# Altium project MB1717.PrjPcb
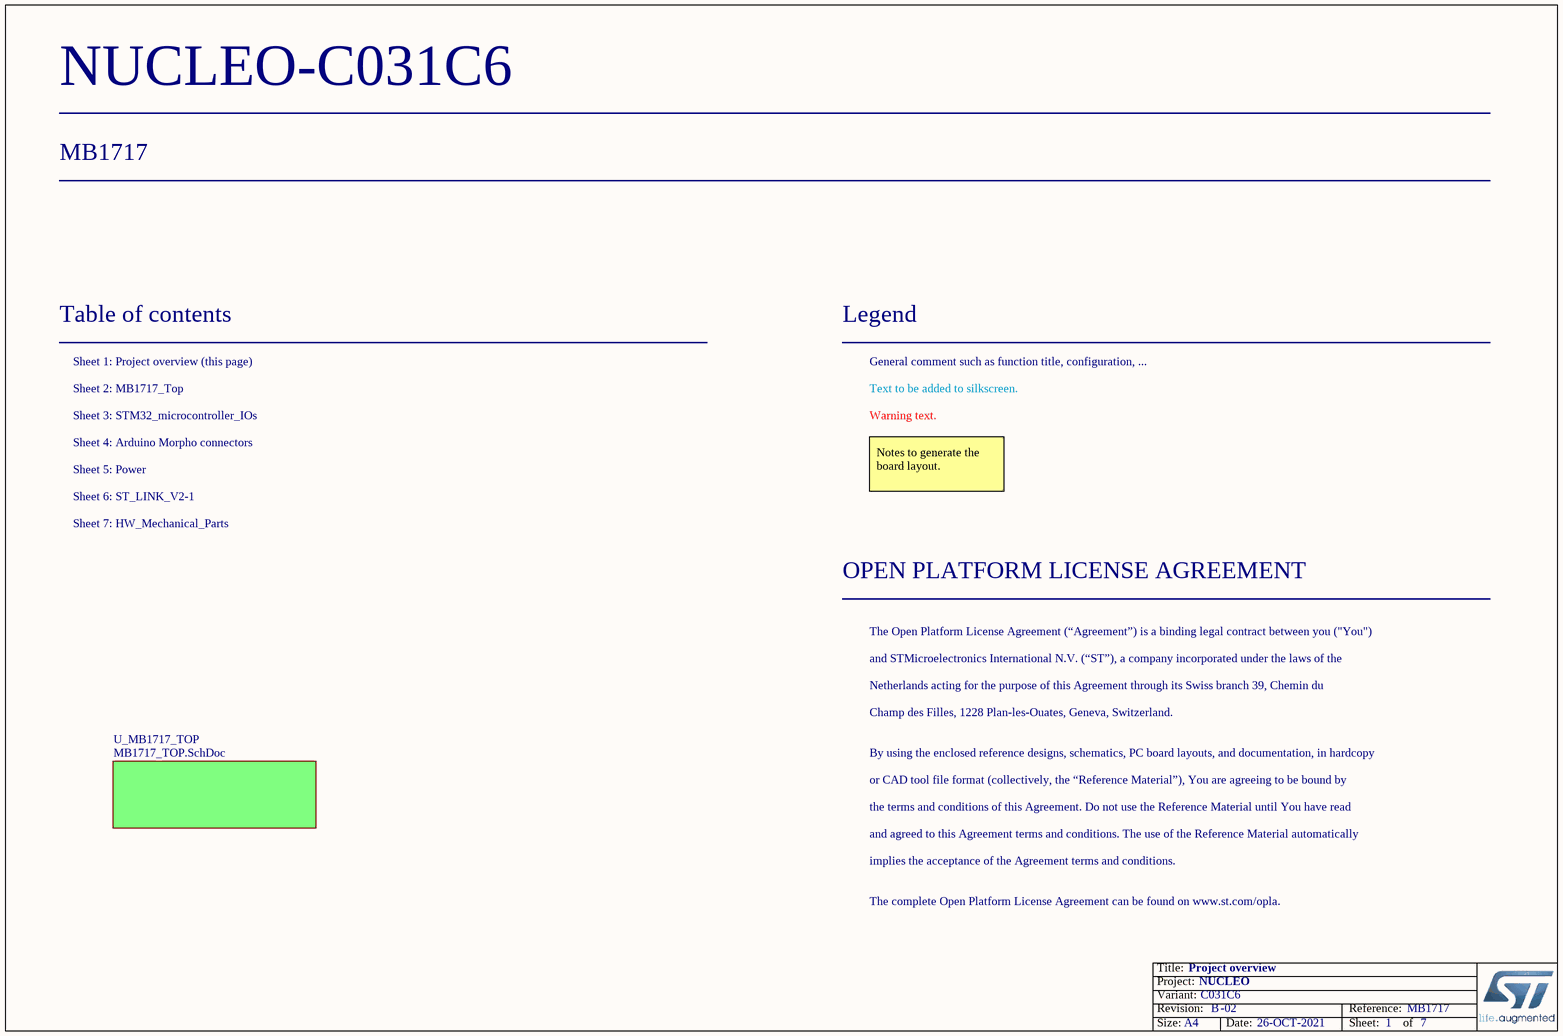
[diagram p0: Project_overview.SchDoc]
VariantName: C031C6; Board_Reference: MB1717; Board_PCB_Revision: B; Board_Name: NUCLEO; Board_Document_Date: 26-OCT-2021; Board_Assembly_Revision: 02
7 sheets, 150 parts. Net scope: flat (ports and power ports of the same name join across sheets).
Board file: MB1717.PcbDoc
Sheets:
  Project_overview.SchDoc
    U_MB1717_TOP = MB1717_TOP.SchDoc
      ST_LINK_V2-1 = ST_LINK_V2-1.SchDoc
      MCU = STM32_microcontroller_IOs.SchDoc
      Power = Power.SchDoc
      HW_Mechanical_Parts = HW_Mechanical_Parts.SchDoc
      U_Arduino_Morpho_connectors = Arduino_Morpho_connectors.SchDoc

## Sheet Project_overview.SchDoc: Project overview
size A4; Date: Not used; ApprovedBy: Not used; CheckedBy: Not used; Author: Not used; CompanyName: STMicroelectronics; DrawnBy: Not used; Engineer: Not used; Organization: Not used; Address1: Not used; Address2: Not used; Address3: Not used; Address4: Not used; DocumentNumber: 1; Revision: Not used; SheetNumber: 1; SheetTotal: 7

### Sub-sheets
U_MB1717_TOP = MB1717_TOP.SchDoc: no entries

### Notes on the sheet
- Table of contents
- Sheet 1: Project overview (this page)
- Legend
- General comment such as function title, configuration, ...
- Sheet 2: MB1717_Top
- Sheet 4: Arduino Morpho connectors
- Sheet 3: STM32_microcontroller_IOs
- Text to be added to silkscreen.
- Warning text.
- Sheet 5: Power
- Sheet 6: ST_LINK_V2-1
- Notes to generate the board layout.
- Sheet 7: HW_Mechanical_Parts
- OPEN PLATFORM LICENSE AGREEMENT
- The Open Platform License Agreement (“Agreement”) is a binding legal contract between you ("You")
- and STMicroelectronics International N.V. (“ST”), a company incorporated under the laws of the
- Netherlands acting for the purpose of this Agreement through its Swiss branch 39, Chemin du
- Champ des Filles, 1228 Plan-les-Ouates, Geneva, Switzerland.
- By using the enclosed reference designs, schematics, PC board layouts, and documentation, in hardcopy
- or CAD tool file format (collectively, the “Reference Material”), You are agreeing to be bound by
- the terms and conditions of this Agreement. Do not use the Reference Material until You have read
- and agreed to this Agreement terms and conditions. The use of the Reference Material automatically
- implies the acceptance of the Agreement terms and conditions.
- The complete Open Platform License Agreement can be found on www.st.com/opla.

## Sheet MB1717_TOP.SchDoc: TOP
size A4; CompanyName: STMicroelectronics; Organization: Microcontrollers Division; SheetNumber: 2; SheetTotal: 7
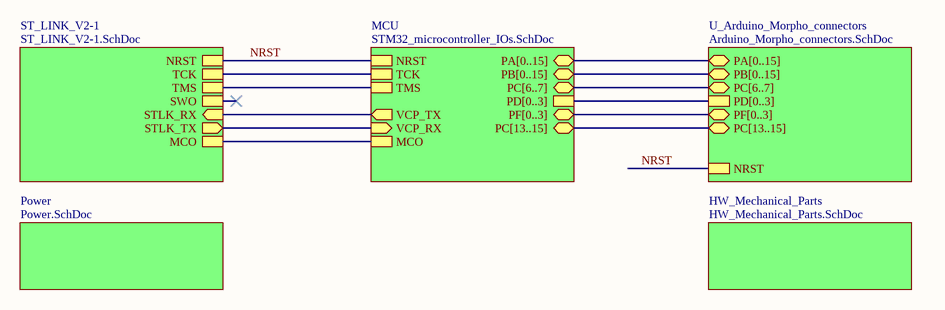
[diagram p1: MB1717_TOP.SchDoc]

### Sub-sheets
HW_Mechanical_Parts = HW_Mechanical_Parts.SchDoc: no entries
MCU = STM32_microcontroller_IOs.SchDoc: NRST, MCO, PA[0..15] (bidir), PB[0..15] (bidir), TCK, TMS, PD[0..3], PC[6..7] (bidir), PC[13..15] (bidir), VCP_RX (in), VCP_TX (out), PF[0..3] (bidir)
Power = Power.SchDoc: no entries
ST_LINK_V2-1 = ST_LINK_V2-1.SchDoc: TMS, TCK, MCO, NRST, STLK_RX (in), STLK_TX (out), SWO
U_Arduino_Morpho_connectors = Arduino_Morpho_connectors.SchDoc: PA[0..15] (bidir), PB[0..15] (bidir), NRST, PD[0..3], PC[6..7] (bidir), PC[13..15] (bidir), PF[0..3] (bidir)

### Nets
NRST: sheet ST_LINK_V2-1/NRST, sheet MCU/NRST, sheet U_Arduino_Morpho_connectors/NRST
(unnamed): sheet ST_LINK_V2-1/TMS, sheet MCU/TMS
(unnamed): sheet ST_LINK_V2-1/TCK, sheet MCU/TCK  [a separate net that carries the same name]
(unnamed): sheet ST_LINK_V2-1/MCO, sheet MCU/MCO  [a separate net that carries the same name]
(unnamed): sheet ST_LINK_V2-1/STLK_RX, sheet MCU/VCP_TX  [a separate net that carries the same name]
(unnamed): sheet ST_LINK_V2-1/STLK_TX, sheet MCU/VCP_RX  [a separate net that carries the same name]

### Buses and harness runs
bus sheet MCU/PA[0..15] = sheet U_Arduino_Morpho_connectors/PA[0..15]
bus sheet MCU/PB[0..15] = sheet U_Arduino_Morpho_connectors/PB[0..15]
bus sheet MCU/PC[6..7] = sheet U_Arduino_Morpho_connectors/PC[6..7]
bus sheet MCU/PC[13..15] = sheet U_Arduino_Morpho_connectors/PC[13..15]
bus sheet MCU/PD[0..3] = sheet U_Arduino_Morpho_connectors/PD[0..3]
bus sheet MCU/PF[0..3] = sheet U_Arduino_Morpho_connectors/PF[0..3]

## Sheet ST_LINK_V2-1.SchDoc: ST_LINK_V2-1
size A4; CompanyName: STMicroelectronics; Organization: Microcontrollers Division; SheetNumber: 6; SheetTotal: 7
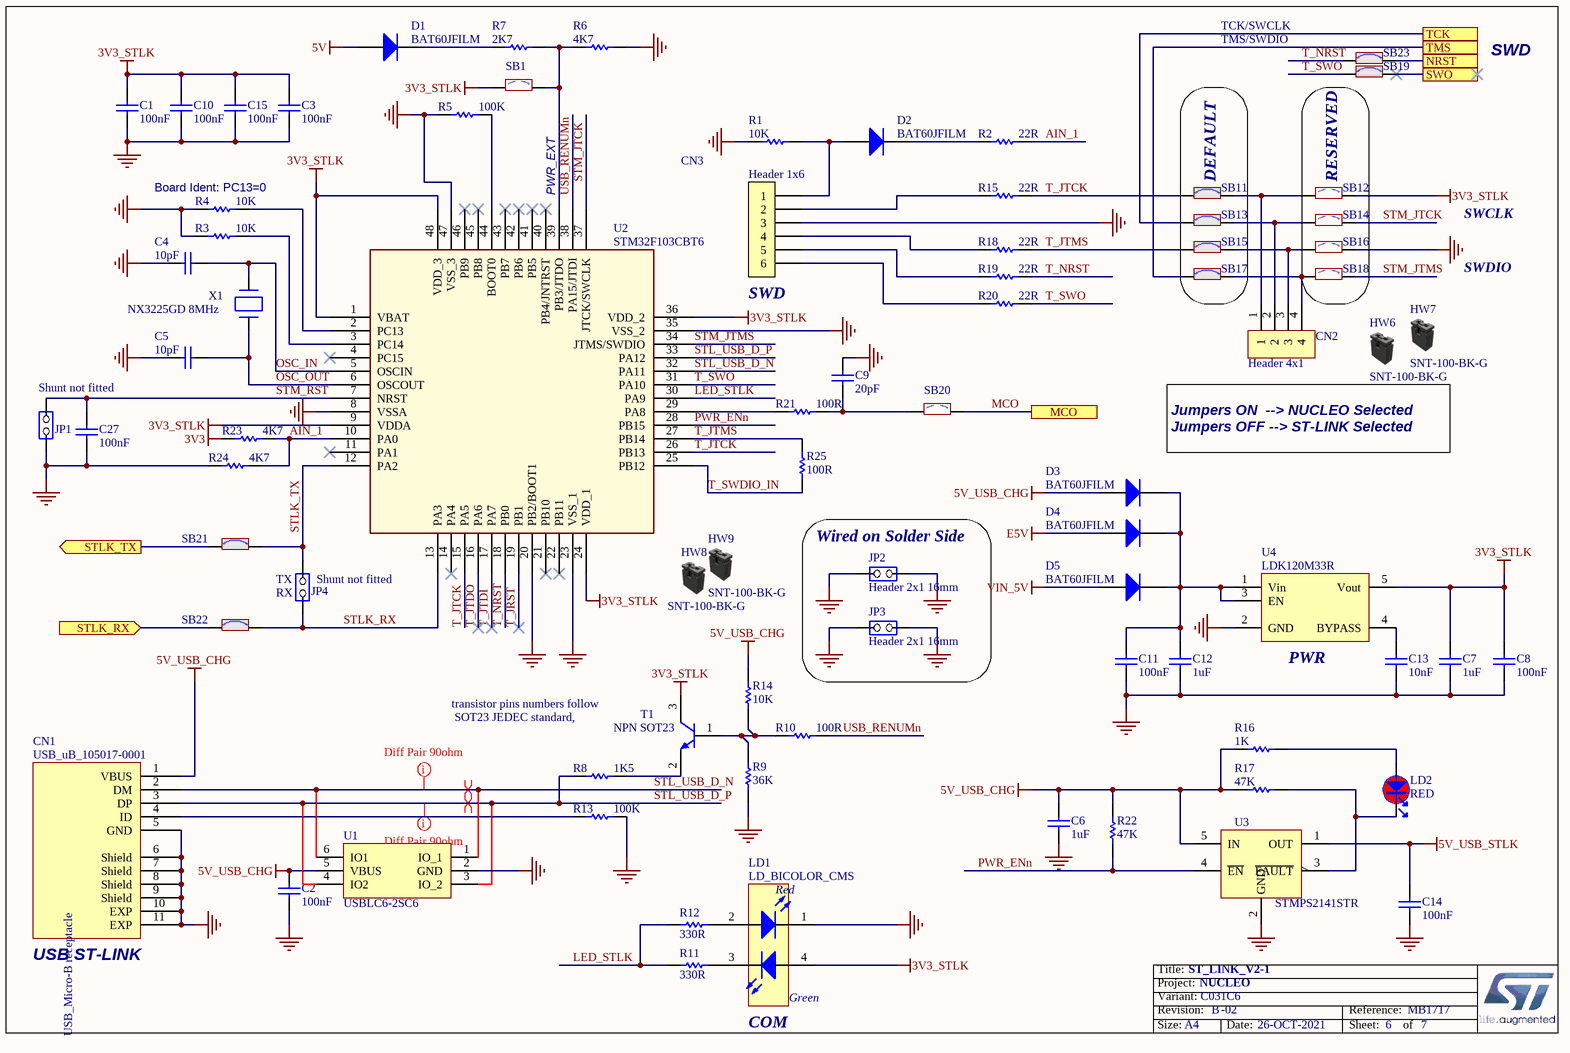
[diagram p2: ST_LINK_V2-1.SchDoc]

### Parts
C1  value 100nF  [C0603]  (hidden comment: Capacitor)
C2  value 100nF  [C0603]  (hidden comment: Capacitor)
C3  value 100nF  [C0603]  (hidden comment: Capacitor)
C4  value 10pF  [C0603]  (hidden comment: Capacitor)
C5  value 10pF  [C0603]  (hidden comment: Capacitor)
C6  value 1uF  [C0603]  (hidden comment: Capacitor)
C7  value 1uF  [C0603]  (hidden comment: Capacitor)
C8  value 100nF  [C0603]  (hidden comment: Capacitor)
C9  value 20pF  [C0603]  (hidden comment: Capacitor)
C10  value 100nF  [C0603]  (hidden comment: Capacitor)
C11  value 100nF  [C0603]  (hidden comment: Capacitor)
C12  value 1uF  [C0603]  (hidden comment: Capacitor)
C13  value 10nF  [C0603]  (hidden comment: Capacitor)
C14  value 100nF  [C0603]  (hidden comment: Capacitor)
C15  value 100nF  [C0603]  (hidden comment: Capacitor)
C27  value 100nF  [C0603]  (hidden comment: Capacitor)
CN1  value USB_uB_105017-0001  [CON_USBMICROB_MOLEX_105017-0001_H2P90]  (hidden comment: USB_uB_105017.0001)
CN2  Header 4x1  [CON_988-JIUBABA_PHFS25-11-04-G0B115-T-1]
CN3  value Header 1x6  [CON_988-JIUBABA_PHFS25-11-06-G0B115-T-1]  (hidden comment: Header 6x1)
D1  BAT60JFILM  [DIO_SOD323]
D2  BAT60JFILM  [DIO_SOD323]
D3  BAT60JFILM  [DIO_SOD323]
D4  BAT60JFILM  [DIO_SOD323]
D5  BAT60JFILM  [DIO_SOD323]
HW6  value SNT-100-BK-G  (hidden comment: Shunt Black 2.54mm)  (mechanical)
HW7  value SNT-100-BK-G  (hidden comment: Shunt Black 2.54mm)  (mechanical)
HW8  value SNT-100-BK-G  (hidden comment: Shunt Black 2.54mm)  (mechanical)
HW9  value SNT-100-BK-G  (hidden comment: Shunt Black 2.54mm)  (mechanical)
JP1  value Shunt not fitted  [CON_SAMTEC_TSW-102-07-G-S]  (hidden comment: Jumper_Header 2x1)
JP2  value Header 2x1 16mm  [CON_SAMTEC_TSW-102-09-X-S]  (hidden comment: Jumper_Header 2x1)
JP3  value Header 2x1 16mm  [CON_SAMTEC_TSW-102-09-X-S]  (hidden comment: Jumper_Header 2x1)
JP4  value Shunt not fitted  [CON_SAMTEC_TSW-102-07-G-S]  (hidden comment: Jumper_Header 2x1)
LD1  LD_BICOLOR_CMS  [LED_BI-GR_HSMF-A201-A00J1]
LD2  value RED  [LED_0603_RED]  (hidden comment: LED_red)
R1  value 10K  [R0603]  (hidden comment: Resistor)
R2  value 22R  [R0603]  (hidden comment: Resistor)
R3  value 10K  [R0603]  (hidden comment: Resistor)
R4  value 10K  [R0603]  (hidden comment: Resistor)
R5  value 100K  [R0603]  (hidden comment: Resistor)
R6  value 4K7  [R0603]  (hidden comment: Resistor)
R7  value 2K7  [R0603]  (hidden comment: Resistor)
R8  value 1K5  [R0603]  (hidden comment: Resistor)
R9  value 36K  [R0603]  (hidden comment: Resistor)
R10  value 100R  [R0603]  (hidden comment: Resistor)
R11  value 330R  [R0603]  (hidden comment: Resistor)
R12  value 330R  [R0603]  (hidden comment: Resistor)
R13  value 100K  [R0603]  (hidden comment: Resistor)
R14  value 10K  [R0603]  (hidden comment: Resistor)
R15  value 22R  [R0603]  (hidden comment: Resistor)
R16  value 1K  [R0603]  (hidden comment: Resistor)
R17  value 47K  [R0603]  (hidden comment: Resistor)
R18  value 22R  [R0603]  (hidden comment: Resistor)
R19  value 22R  [R0603]  (hidden comment: Resistor)
R20  value 22R  [R0603]  (hidden comment: Resistor)
R21  value 100R  [R0603]  (hidden comment: Resistor)
R22  value 47K  [R0603]  (hidden comment: Resistor)
R23  value 4K7  [R0603]  (hidden comment: Resistor)
R24  value 4K7  [R0603]  (hidden comment: Resistor)
R25  value 100R  [R0603]  (hidden comment: Resistor)
SB1  SB_OFF  [SOLDER-BRIDGE_R0603-0R]  (value not drawn)
SB11  SB_ON  [SOLDER-BRIDGE_R0603-0R]  (value not drawn)
SB12  SB_OFF  [SOLDER-BRIDGE_R0603-0R]  (value not drawn)
SB13  SB_ON  [SOLDER-BRIDGE_R0603-0R]  (value not drawn)
SB14  SB_OFF  [SOLDER-BRIDGE_R0603-0R]  (value not drawn)
SB15  SB_ON  [SOLDER-BRIDGE_R0603-0R]  (value not drawn)
SB16  SB_OFF  [SOLDER-BRIDGE_R0603-0R]  (value not drawn)
SB17  SB_ON  [SOLDER-BRIDGE_R0603-0R]  (value not drawn)
SB18  SB_OFF  [SOLDER-BRIDGE_R0603-0R]  (value not drawn)
SB19  SB_ON  [SOLDER-BRIDGE_R0603-0R]  (value not drawn)
SB20  SB_OFF  [SOLDER-BRIDGE_R0603-0R]  (value not drawn)
SB21  SB_ON  [SOLDER-BRIDGE_R0603-0R]  (value not drawn)
SB22  SB_ON  [SOLDER-BRIDGE_R0603-0R]  (value not drawn)
SB23  SB_ON  [SOLDER-BRIDGE_R0603-0R]  (value not drawn)
T1  value NPN SOT23  [NPN_SOT23]  (hidden comment: 9013-SOT23)
U1  USBLC6-2SC6  [ESD_SOT23-6L]
U2  STM32F103CBT6  [ICC_LQFP48_7X7_P050]
U3  STMPS2141STR  [MOS_SOT23-5L]
U4  LDK120M33R  [REG_SOT23-5L]
X1  value NX3225GD 8MHz  [CRY_NX3225GD_2P]  (hidden comment: XTAL_2_PINS)

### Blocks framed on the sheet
DEFAULT: SB11 SB13 SB15 SB17
RESERVED: SB12 SB14 SB16 SB18
Wired on Solder Side: JP2 JP3

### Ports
MCO, NRST, STLK_RX (in), STLK_TX (out), SWO, TCK, TMS

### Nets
3V3: R23.1
3V3_STLK: C1.2 C3.2 C7.2 C8.2 C10.2 C15.2 LD1.4(YellowGreen_anode) SB1.1 SB12.2 T1.3(C) U2.1(VBAT) U2.9(VDDA) U2.24(VDD_1) U2.36(VDD_2) U2.48(VDD_3) U4.5(Vout)
5V: D1.1(A)
5V_USB_CHG: C2.2 C6.2 CN1.1(VBUS) D3.1(A) R14.2 R16.2 R17.2 R22.2 U1.5(VBUS) U3.5(IN)
5V_USB_STLK: C14.2 U3.1(OUT)
E5V: D4.1(A)
GND: C1.1 C2.1 C3.1 C4.1 C5.1 C6.1 C7.1 C8.1 C9.2 C10.1 C11.1 C12.1 C13.1 C14.1 C15.1 C27.2 CN1.5(GND) CN1.6(Shield) CN1.7(Shield) CN1.8(Shield) CN1.9(Shield) CN1.10(EXP) CN1.11(EXP) CN3.3 JP1.2(NO) JP2.1(COMMON) JP2.2(NO) JP3.1(COMMON) JP3.2(NO) LD1.1(RED_cathode) R1.2 R3.1 R4.1 R5.1 R6.2 R9.1 R13.2 R24.1 SB16.2 U1.2(GND) U2.8(VSSA) U2.20(PB2/BOOT1) U2.23(VSS_1) U2.35(VSS_2) U2.47(VSS_3) U3.2(GND) U4.2(GND)
VIN_5V: D5.1(A)
AIN_1: R2.2 R23.2 R24.2 U2.10(PA0)
LED_STLK: R11.1 R12.1 U2.30(PA9)
MCO: SB20.2 ; port MCO
NRST: SB23.2 ; port NRST
OSC_IN: C4.2 U2.5(OSCIN) X1.2(X2)
OSC_OUT: C5.2 U2.6(OSCOUT) X1.1(X1)
PA13: SB17.1 ; port TMS
PA14: SB13.1 ; port TCK
PWR_ENn: R22.1 U2.28(PB15) U3.4(~{EN})
STL_USB_D_N: CN1.2(DM) U1.1(IO_1) U1.6(IO1) U2.32(PA11)
STL_USB_D_P: CN1.3(DP) R8.1 U1.3(IO_2) U1.4(IO2) U2.33(PA12)
STLK_RX: JP4.1(COMMON) SB22.2 U2.13(PA3)
STLK_TX: JP4.2(NO) SB21.2 U2.12(PA2)
STM_JTCK: SB14.2 U2.37(JTCK/SWCLK)
STM_JTMS: SB18.2 U2.34(JTMS/SWDIO)
STM_RST: C27.1 JP1.1(COMMON) U2.7(NRST)
T_JRST: U2.19(PB1)
T_JTCK: R15.2 SB11.1 U2.15(PA5) U2.26(PB13)
T_JTDI: U2.17(PA7)
T_JTDO: U2.16(PA6)
T_JTMS: R18.2 R25.2 SB15.1 U2.27(PB14)
T_NRST: R19.2 SB23.1 U2.18(PB0)
T_SWDIO_IN: R25.1 U2.25(PB12)
T_SWO: R20.2 SB19.1 U2.31(PA10)
USB_RENUMn: R10.2 U2.38(PA15/JTDI)
NetC9_1: C9.1 R21.2 SB20.1
NetC11_2: C11.2 C12.2 D3.2(K) D4.2(K) D5.2(K) U4.1(Vin) U4.3(EN)
NetC13_2: C13.2 U4.4(BYPASS)
NetCN1_4: CN1.4(ID) R13.1
NetCN2_1: CN2.1 SB11.2 SB12.1
NetCN2_2: CN2.2 SB13.2 SB14.1
NetCN2_3: CN2.3 SB15.2 SB16.1
NetCN2_4: CN2.4 SB17.2 SB18.1
NetCN3_1: CN3.1 D2.1(A) R1.1
NetCN3_2: CN3.2 R15.1
NetCN3_4: CN3.4 R18.1
NetCN3_5: CN3.5 R19.1
NetCN3_6: CN3.6 R20.1
NetD1_2: D1.2(K) R7.1
NetD2_2: D2.2(K) R2.1
NetLD1_2: LD1.2(Red_anode) R12.2
NetLD1_3: LD1.3(YellowGreen_cathode) R11.2
NetLD2_1: LD2.1 R16.1
NetLD2_2: LD2.2 R17.1 U3.3(~{FAULT})
NetR3_2: R3.2 U2.3(PC14)
NetR4_2: R4.2 U2.2(PC13)
NetR5_2: R5.2 U2.44(BOOT0)
NetR6_1: R6.1 R7.2 SB1.2 U2.39(PB3/JTDO)
NetR8_2: R8.2 T1.2(E)
NetR9_2: R9.2 R10.1 R14.1 T1.1(B)
NetR21_1: R21.1 U2.29(PA8)
NetSB19_2: SB19.2 ; port SWO
NetSB21_1: SB21.1 ; port STLK_TX
NetSB22_1: SB22.1 ; port STLK_RX

Not connected (* = marked no-connect by the designer): U2 4(PC15)* 11(PA1)* 14(PA4)* 21(PB10)* 22(PB11)* 40(PB4/JNTRST)* 41(PB5)* 42(PB6)* 43(PB7)* 45(PB8)* 46(PB9)*

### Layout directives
mark named Diff Pair 90ohm: STL_USB_D_N, STL_USB_D_P
differential pair: STL_USB_D_N, STL_USB_D_P

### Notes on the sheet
- TCK/SWCLK
- TMS/SWDIO
- SWD
- (near R4) Board Ident: PC13=0
- PWR_EXT
- SWCLK
- (near CN3) SWD
- SWDIO
- Jumpers ON  --> NUCLEO Selected
  Jumpers OFF --> ST-LINK Selected
- (near JP4) TX
- (near JP4) RX
- (near U4) PWR
- (near T1) transistor pins numbers follow
  SOT23 JEDEC standard,
- (near CN1) USB ST-LINK
- COM

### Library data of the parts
C1-C3 C8 C10 C11 C14 C15 C27 = MCD-00211: Capacitor, MLCC, 100nF, 16V, X7R, +/-10%, 0603, T=0,8mm; Manufacturer_Part_Number: CC0603KRX7R7BB104; Manufacturer: YAGEO; Alternate_Manufacturer_Part_Number: GCM155R71C104KA55D; Alternate_Manufacturer: MURATA; Part_Preference: Recommended; ECCN_US: EAR99; ECCN_EU: NEC; Provided_By: SUBCO; Order_Code_RS: 669-8763
C4 C5 = MCD-00637: Capacitor, MLCC, 10pF, 50V, NPO, +/-5%, 0603, T=0,8mm; Manufacturer_Part_Number: CC0603JRNPO9BN100; Manufacturer: YAGEO; Alternate_Manufacturer_Part_Number: GCM155R71C104KA55D; Alternate_Manufacturer: MURATA; Part_Preference: Recommended; ECCN_US: EAR99; ECCN_EU: NEC; Provided_By: SUBCO
C6 C7 C12 = MCD-00010: Capacitor, MLCC, 1uF, 16V, X5R, +/-10%, 0603, T=0,8mm; Manufacturer_Part_Number: CC0603KRX5R7BB105; Manufacturer: YAGEO; Alternate_Manufacturer_Part_Number: GCM155R71C104KA55D; Alternate_Manufacturer: MURATA; Part_Preference: Recommended; ECCN_US: EAR99; ECCN_EU: NEC; Provided_By: SUBCO
C9 = MCD-00638: Capacitor, MLCC, 20pF, 50V, NPO, +/-5%, 0603, T=0,8mm; Manufacturer_Part_Number: CC0603JRNPO9BN200; Manufacturer: YAGEO; Alternate_Manufacturer_Part_Number: GCM155R71C104KA55D; Alternate_Manufacturer: MURATA; Part_Preference: Recommended; ECCN_US: EAR99; ECCN_EU: NEC; Provided_By: SUBCO
C13 = MCD-00017: Capacitor, MLCC, 10nF, 50V, X7R, +/-10%, 0603, T=0.8mm; Manufacturer_Part_Number: CC0603KRX7R9BB103; Manufacturer: YAGEO; Alternate_Manufacturer_Part_Number: GCM155R71C104KA55D; Alternate_Manufacturer: MURATA; Part_Preference: Recommended; ECCN_US: EAR99; ECCN_EU: NEC; Provided_By: SUBCO; Order_Code_RS: 616-9537
CN1 = MCD-00028: USB-MICRO-B, 0.65mm, RA, SMT, Bottom Mount,; Part_Type: Connector; Manufacturer_Part_Number: 1050170001; Manufacturer: MOLEX; Part_Preference: Recommended; Provided_By: SUBCO
CN2 = MCD-00313: Header, 4x1, 2.54mm, VR, TH, Height 6mm/3mm; Part_Type: Connector; Manufacturer_Part_Number: PHFS25-11-04-G0B115-T-1; Manufacturer: JIUBABA; Alternate_Manufacturer_Part_Number: 313104S1411160; Alternate_Manufacturer: LIANYI; Part_Preference: Not recommended
CN3 = MCD-00316: Header, 6x1, 2.54mm, VR, TH, Height 6mm/3mm; Part_Type: Connector; Manufacturer_Part_Number: PHFS25-11-06-G0B115-T-1; Manufacturer: JIUBABA; Alternate_Manufacturer_Part_Number: 313106S1411160; Alternate_Manufacturer: LIANYI; Part_Preference: Not recommended; Provided_By: SUBCO
D1 = MCD-00034: Manufacturer: STMICROELECTRONICS; Part_Type: Diode; BMS_Part_Number: 9151097; Part_Preference: Recommended; Manufacturer_HQ_COO: EU; ECCN_US: EAR99; ECCN_EU: NEC; Provided_By: Subcon; Initial_Board_Reference: mb1274
D2-D5 = MCD-00034: Part_Type: Diode; Manufacturer: STMICROELECTRONICS; BMS_Part_Number: 9151097; Part_Preference: Recommended; Manufacturer_HQ_COO: EU; ECCN_US: EAR99; ECCN_EU: NEC; Provided_By: Subcon; Initial_Board_Reference: mb1274
HW6-HW9 = MCD-00043: SHUNT 2.54mm BLACK; Manufacturer: SAMTEC; Part_Type: Misc; Alternate_Manufacturer_Part_Number: 316102S111A; Alternate_Manufacturer: JIUBABA; Part_Preference: Recommended
JP1 JP4 = MCD-00045: Header, 2x1, 2,54mm, VR, TH, Height 5.84mm/2.54mm; Part_Type: Connector; Manufacturer_Part_Number: TSW-102-07-G-S; Manufacturer: SAMTEC; Alternate_Manufacturer_Part_Number: 313102S111116;313102S111116; Alternate_Manufacturer: JIUBABA; LIANYI; Part_Preference: Recommended
JP2 JP3 = MCD-00214: Header, 2x1, 2,54mm, VR, TH, Height 5.84mm/10.16mm; Part_Type: Connector; Manufacturer_Part_Number: TSW-102-09-G-S; Manufacturer: SAMTEC; Part_Preference: Recommended
LD1 = MCD-02402: LED Bicolor; Part_Type: Display; Manufacturer_Part_Number: 67-22sursygc-s530-a2-tr8; Manufacturer: EVERLIGHT; Alternate_Manufacturer_Part_Number: LE-RGW35280; Alternate_Manufacturer: EVERLUCK; Part_Preference: Alternate; Alternate_Internal_Part_Number: MCD-00051; ECCN_US: EAR99; ECCN_EU: NEC; Provided_By: SUBCO; Alternate_EMS: C
LD2 = MCD-00049: LED, Red, 0603; Manufacturer_Part_Number: 19-213-R6C-AP1Q2B/3T; Manufacturer: EVERLIGHT; Part_Type: Display; Alternate_Manufacturer_Part_Number: LS Q976-NR-1; Alternate_Manufacturer: OSRAM OPTO SEMICONDUCTORS; Part_Preference: Recommended; Provided_By: SUBCO
R1 R3 R4 R14 = MCD-00220: Resistor,10K,0603,1%,1/10W; Manufacturer_Part_Number: RC0603FR-0710KL; Manufacturer: YAGEO; Alternate_Manufacturer_Part_Number: RT0402FRE07100KL; Part_Preference: Recommended; ECCN_US: EAR99; ECCN_EU: NEC; Provided_By: SUBCO
R2 R15 R18-R20 = MCD-00066: Resistor,22R,0603,1%,1/10W; Manufacturer_Part_Number: RC0603FR-0722RL; Manufacturer: YAGEO; Alternate_Manufacturer_Part_Number: RT0402FRE07100KL; Part_Preference: Recommended; ECCN_US: EAR99; ECCN_EU: NEC; Provided_By: SUBCO
R5 R13 = MCD-00223: Resistor,100K,0603,1%,1/10W; Manufacturer_Part_Number: RC0603FR-07100KL; Manufacturer: YAGEO; Alternate_Manufacturer_Part_Number: RT0402FRE07100KL; Part_Preference: Recommended; ECCN_US: EAR99; ECCN_EU: NEC; Provided_By: SUBCO
R6 R23 R24 = MCD-00219: Resistor,4K7,0603,1%,1/10W; Manufacturer_Part_Number: RC0603FR-074K7L; Manufacturer: YAGEO; Alternate_Manufacturer_Part_Number: RT0402FRE07100KL; Part_Preference: Recommended; ECCN_US: EAR99; ECCN_EU: NEC; Provided_By: SUBCO
R7 = MCD-00218: Resistor,2K7,0603,1%,1/10W; Manufacturer_Part_Number: RC0603FR-072K7L; Manufacturer: YAGEO; BMS_Part_Number: 9129767; Alternate_Manufacturer_Part_Number: RT0402FRE07100KL; Part_Preference: Recommended; ECCN_US: EAR99; ECCN_EU: NEC; Provided_By: SUBCO
R8 = MCD-00217: Resistor,1K5,0603,1%,1/10W; Manufacturer_Part_Number: RC0603FR-071K5L; Manufacturer: YAGEO; BMS_Part_Number: 9129766; Alternate_Manufacturer_Part_Number: RT0402FRE07100KL; Part_Preference: Recommended; ECCN_US: EAR99; ECCN_EU: NEC; Provided_By: SUBCO
R9 = MCD-00221: Resistor,36K,0603,1%,1/10W; Manufacturer_Part_Number: RC0603FR-0736KL; Manufacturer: YAGEO; Alternate_Manufacturer_Part_Number: RT0402FRE07100KL; Part_Preference: Recommended; ECCN_US: EAR99; ECCN_EU: NEC; Provided_By: SUBCO
R10 R21 R25 = MCD-00224: Resistor,100R,0603,1%,1/10W; Manufacturer_Part_Number: RC0603FR-07100RL; Manufacturer: YAGEO; Alternate_Manufacturer_Part_Number: RT0402FRE07100KL; Part_Preference: Recommended; ECCN_US: EAR99; ECCN_EU: NEC; Provided_By: SUBCO
R11 R12 = MCD-00197: Resistor,330R,0603,1%,1/10W; Manufacturer_Part_Number: RC0603FR-07330RL; Manufacturer: YAGEO; BMS_Part_Number: 9129729; Alternate_Manufacturer_Part_Number: RT0402FRE07100KL; Part_Preference: Recommended; ECCN_US: EAR99; ECCN_EU: NEC; Provided_By: SUBCO
R16 = MCD-00070: Resistor,1K,0603,1%,1/10W; Manufacturer_Part_Number: RC0603FR-071KL; Manufacturer: YAGEO; Alternate_Manufacturer_Part_Number: RT0402FRE07100KL; Part_Preference: Recommended; ECCN_US: EAR99; ECCN_EU: NEC; Provided_By: SUBCO
R17 R22 = MCD-00222: Resistor,47K,0603,1%,1/10W; Manufacturer_Part_Number: RC0603FR-0747KL; Manufacturer: YAGEO; Alternate_Manufacturer_Part_Number: RT0402FRE07100KL; Part_Preference: Recommended; ECCN_US: EAR99; ECCN_EU: NEC; Provided_By: SUBCO
SB1 SB12 SB14 SB16 SB18 SB20 = MCD-00072: Solder Bridge OFF; Part_Type: Misc; Manufacturer_Part_Number: RC0603JR-070RL; Manufacturer: YAGEO; Part_Preference: Recommended
SB11 SB13 SB15 SB17 SB19 SB21-SB23 = MCD-00071: Solder Bridge ON; Part_Type: Misc; Manufacturer_Part_Number: RC0603JR-070RL; Manufacturer: YAGEO; Part_Preference: Recommended; Provided_By: SUBCO
T1 = MCD-00073: NPN Bipolar Transistor; Part_Type: IC; Manufacturer_Part_Number: BSR14; Manufacturer: ON SEMICONDUCTOR; Alternate_Manufacturer_Part_Number: MMBT2222LT1G / MMBT2222ALT1G / MMBT2222ALT3G; Part_Preference: Recommended; ECCN_US: EAR99; ECCN_EU: NEC; Provided_By: Subcon; Initial_Board_Reference: mb1274
U1 = MCD-00163: Very low capacitance ESD protection; Part_Type: IC; Manufacturer: STMICROELECTRONICS; BMS_Part_Number: 9151075; Part_Preference: Recommended; Manufacturer_HQ_COO: EU
U2 = MCD-00085: Medium-density performance line ARM-based 32-bit MCU with 128KB Flash; Manufacturer: STMICROELECTRONICS; Part_Type: IC; BMS_Part_Number: 9175111; Part_Preference: Recommended; Manufacturer_HQ_COO: EU; ECCN_US: 3A991A2; ECCN_EU: NEC; Provided_By: SUBCO with ST control
U3 = MCD-00083: Enhanced single channel power switches with active low enable pin; Part_Type: IC; Manufacturer: STMICROELECTRONICS; Alternate_Manufacturer_Part_Number: TPS2041C; Alternate_Manufacturer: TEXAS INSTRUMENTS; BMS_Part_Number: 9159003; Part_Preference: Recommended; Manufacturer_HQ_COO: EU
U4 = MCD-00663: 200 mA low quiescent current very low noise LDO; Part_Type: IC; Manufacturer: STMICROELECTRONICS; BMS_Part_Number: 9176330; Part_Preference: Recommended; Manufacturer_HQ_COO: EU
X1 = MCD-00092: Crystal 8MHz, 8pF, +-20ppm, 500ohms max,  SMD; Part_Type: Crystal oscillator; Manufacturer_Part_Number: NX3225GD 8MHz EXS00A-CG04874; Manufacturer: NDK; BMS_Part_Number: 9157029; Part_Preference: Recommended; ECCN_US: EAR99; ECCN_EU: NEC; Provided_By: SUBCO

## Sheet STM32_microcontroller_IOs.SchDoc: STM32_microcontroller_IOs
size A4; CompanyName: STMicroelectronics; Organization: Microcontrollers Division; SheetNumber: 3; SheetTotal: 7
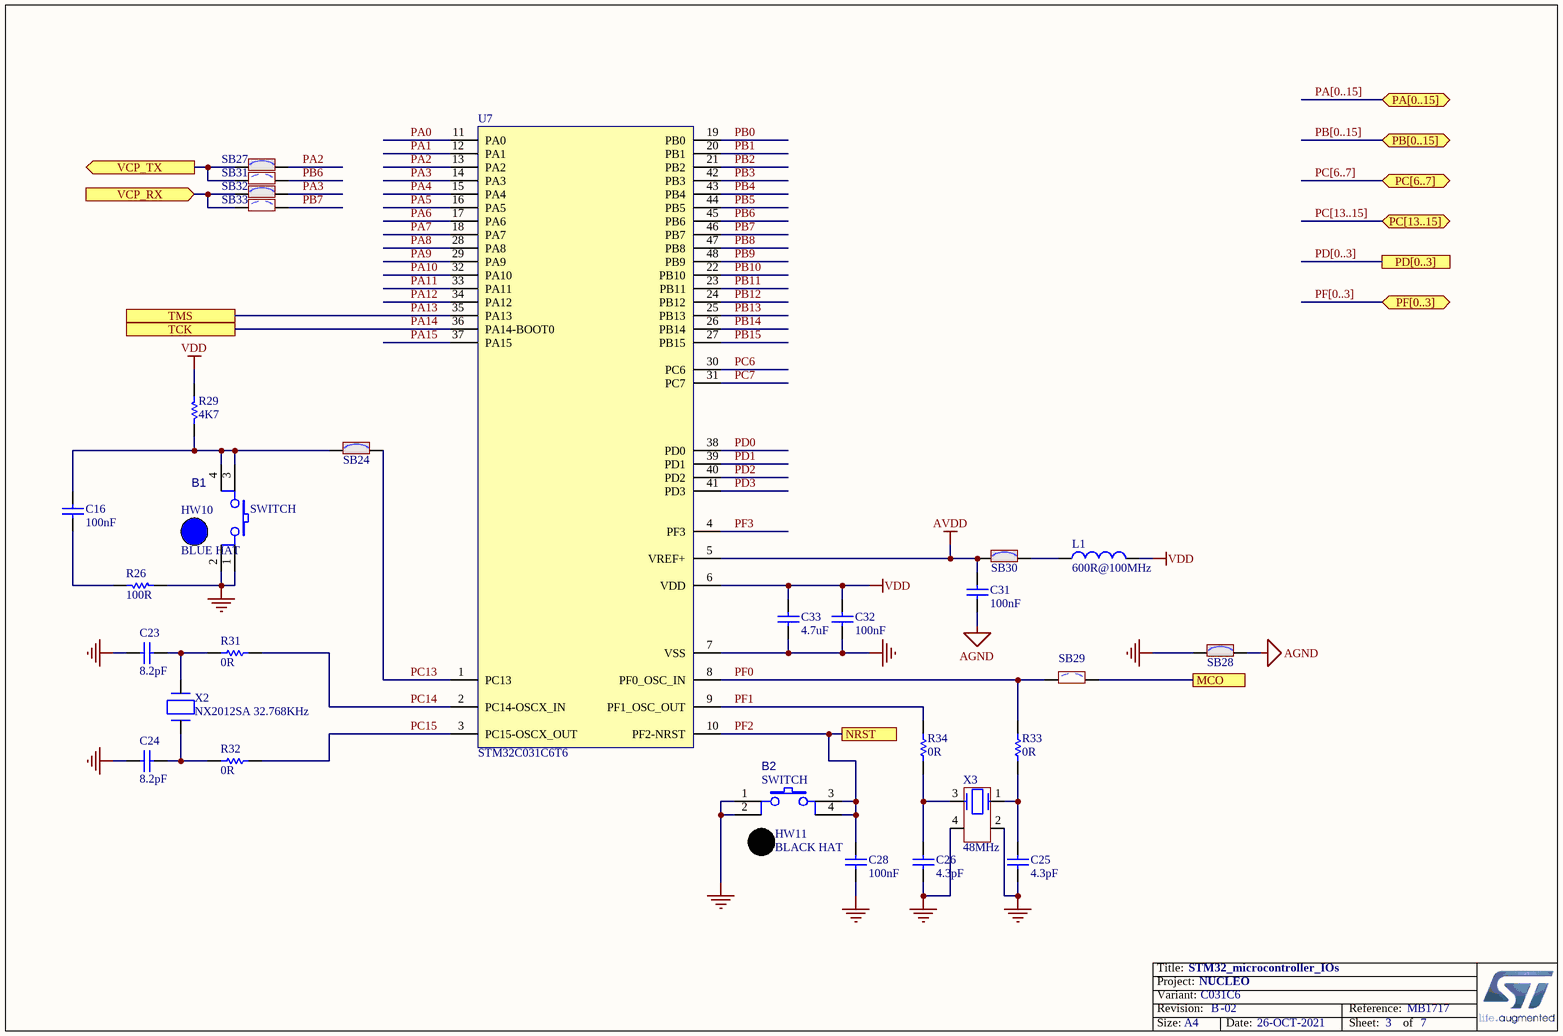
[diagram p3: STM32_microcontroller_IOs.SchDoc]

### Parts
B1  value SWITCH  [SWI_WEALTHMETAL_TD-0341_4P_BLUE]  (hidden comment: SW_PUSH_SMD)
B2  value SWITCH  [SWI_WEALTHMETAL_TD-0341_4P_BLACK]  (hidden comment: SW_PUSH_SMD)
C16  value 100nF  [C0603]  (hidden comment: Capacitor)
C23  value 8.2pF  [C0402]  (hidden comment: Capacitor)
C24  value 8.2pF  [C0402]  (hidden comment: Capacitor)
C25  value 4.3pF  [C0402]  (hidden comment: Capacitor)
C26  value 4.3pF  [C0402]  (hidden comment: Capacitor)
C28  value 100nF  [C0603]  (hidden comment: Capacitor)
C31  value 100nF  [C0603]  (hidden comment: Capacitor)
C32  value 100nF  [C0603]  (hidden comment: Capacitor)
C33  value 4.7uF  [C0603]  (hidden comment: Capacitor)
HW10  value BLUE HAT  (hidden comment: BUTTON_HAT_BLUE)  (mechanical)
HW11  value BLACK HAT  (hidden comment: BUTTON_HAT_BLACK)  (mechanical)
L1  value 600R@100MHz  [L0603]  (hidden comment: BEAD)
R26  value 100R  [R0603]  (hidden comment: Resistor)
R29  value 4K7  [R0603]  (hidden comment: Resistor)
R31  value 0R  [R0402]  (hidden comment: Resistor)
R32  value 0R  [R0402]  (hidden comment: Resistor)
R33  value 0R  [R0402]  (hidden comment: Resistor)
R34  value 0R  [R0402]  (hidden comment: Resistor)
SB24  SB_ON  [SOLDER-BRIDGE_R0603-0R]  (value not drawn)
SB27  SB_ON  [SOLDER-BRIDGE_R0603-0R]  (value not drawn)
SB28  SB_ON  [SOLDER-BRIDGE_R0603-0R]  (value not drawn)
SB29  SB_OFF  [SOLDER-BRIDGE_R0603-0R]  (value not drawn)
SB30  SB_ON  [SOLDER-BRIDGE_R0603-0R]  (value not drawn)
SB31  SB_OFF  [SOLDER-BRIDGE_R0603-0R]  (value not drawn)
SB32  SB_ON  [SOLDER-BRIDGE_R0603-0R]  (value not drawn)
SB33  SB_OFF  [SOLDER-BRIDGE_R0603-0R]  (value not drawn)
U7  STM32C031C6T6  [ICC_LQFP48_7X7_P050]
X2  value NX2012SA 32.768KHz  [CRY_NX2012SA_2P]  (hidden comment: XTAL_2_PINS)
X3  value 48MHz  [CRY_NX1612SA_4P]  (hidden comment: XTAL_4_PINS)

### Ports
MCO, NRST, PA[0..15] (bidir), PB[0..15] (bidir), PC[6..7] (bidir), PC[13..15] (bidir), PD[0..3], PF[0..3] (bidir), TCK, TMS, VCP_RX (in), VCP_TX (out)

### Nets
AGND: C31.1 SB28.2
AVDD: C31.2 SB30.1 U7.5(VREF+)
GND: B1.1 B1.2 B2.1 B2.2 C23.1 C24.1 C25.1 C26.1 C28.1 C32.1 C33.1 R26.1 SB28.1 U7.7(VSS) X3.2 X3.4
VDD: C32.2 C33.2 L1.2 R29.2 U7.6(VDD)
MCO: SB29.2 ; port MCO
PA0: U7.11(PA0)
PA1: U7.12(PA1)
PA2: SB27.2 U7.13(PA2)
PA3: SB32.2 U7.14(PA3)
PA4: U7.15(PA4)
PA5: U7.16(PA5)
PA6: U7.17(PA6)
PA7: U7.18(PA7)
PA8: U7.28(PA8)
PA9: U7.29(PA9)
PA10: U7.32(PA10)
PA11: U7.33(PA11)
PA12: U7.34(PA12)
PA13: U7.35(PA13) ; port TMS
PA14: U7.36(PA14-BOOT0) ; port TCK
PA15: U7.37(PA15)
PB0: U7.19(PB0)
PB1: U7.20(PB1)
PB2: U7.21(PB2)
PB3: U7.42(PB3)
PB4: U7.43(PB4)
PB5: U7.44(PB5)
PB6: SB31.2 U7.45(PB6)
PB7: SB33.2 U7.46(PB7)
PB8: U7.47(PB8)
PB9: U7.48(PB9)
PB10: U7.22(PB10)
PB11: U7.23(PB11)
PB12: U7.24(PB12)
PB13: U7.25(PB13)
PB14: U7.26(PB14)
PB15: U7.27(PB15)
PC6: U7.30(PC6)
PC7: U7.31(PC7)
PC13: SB24.1 U7.1(PC13)
PC14: R31.2 U7.2(PC14-OSCX_IN)
PC15: R32.2 U7.3(PC15-OSCX_OUT)
PD0: U7.38(PD0)
PD1: U7.39(PD1)
PD2: U7.40(PD2)
PD3: U7.41(PD3)
PF0: R33.2 SB29.1 U7.8(PF0_OSC_IN)
PF1: R34.2 U7.9(PF1_OSC_OUT)
PF2: B2.3 B2.4 C28.2 U7.10(PF2-NRST) ; port NRST  [project net NRST]
PF3: U7.4(PF3)
NetB1_3: B1.3 B1.4 C16.2 R29.1 SB24.2
NetC16_1: C16.1 R26.2
NetC23_2: C23.2 R31.1 X2.2(X2)
NetC24_2: C24.2 R32.1 X2.1(X1)
NetC25_2: C25.2 R33.1 X3.1
NetC26_2: C26.2 R34.1 X3.3
NetL1_1: L1.1 SB30.2
NetSB27_1: SB27.1 SB31.1 ; port VCP_TX
NetSB32_1: SB32.1 SB33.1 ; port VCP_RX

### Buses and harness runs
bus PA[0..15] = port PA[0..15]
bus PB[0..15] = port PB[0..15]
bus PC[6..7] = port PC[6..7]
bus PC[13..15] = port PC[13..15]
bus PD[0..3] = port PD[0..3]
bus PF[0..3] = port PF[0..3]

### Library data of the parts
B1 = MCD-00002: Push Button, NC, 0.1A, 24V, Blue; Part_Type: Misc; Manufacturer_Part_Number: TD-0341X-GO0; Manufacturer: WEALTHMETAL; Part_Preference: Not recommended
B2 = MCD-00001: Push Button, NC, 0.1A, 24V, Black; Part_Type: Misc; Manufacturer_Part_Number: TD-0341X-A00; Manufacturer: WEALTHMETAL; Part_Preference: Not recommended
C16 C28 C31 C32 = MCD-00211: as C1 on sheet ST_LINK_V2-1
C23 C24 = MCD-01932: Capacitor, MLCC, 8.2pF, 50V, NPO, +/- 0.25pF, 0402, T=0,5mm; Manufacturer_Part_Number: CC0402CRNPO9BN8R2; Manufacturer: YAGEO; Part_Preference: Recommended; ECCN_US: EAR99; ECCN_EU: NEC; Provided_By: SUBCO
C25 C26 = MCD-01706: Capacitor, MLCC, 4.3pF, 50V, NPO, +/-0.25pF, 0402, T=0,5mm; Manufacturer_Part_Number: CC0402CRNPO9BN4R3; Manufacturer: YAGEO; Alternate_Manufacturer_Part_Number: GCM155R71C104KA55D; Alternate_Manufacturer: MURATA; Part_Preference: Recommended; ECCN_US: EAR99; ECCN_EU: NEC; Provided_By: SUBCO
C33 = MCD-00009: Capacitor, MLCC, 4.7uF, 16V, X5R, +/-10%, 0603, T=0.8mm; Manufacturer_Part_Number: CC0603KRX5R7BB475; Manufacturer: YAGEO; Alternate_Manufacturer_Part_Number: GCM155R71C104KA55D; Alternate_Manufacturer: MURATA; Part_Preference: Recommended; ECCN_US: EAR99; ECCN_EU: NEC; Provided_By: SUBCO
HW10 = MCD-00634: Blue Hat for switch TD0341X-G01-BLU; Part_Type: Misc; Manufacturer_Part_Number: 988.16.09.3.00002_SH-517; Manufacturer: JIUBABA; Part_Preference: Not recommended
HW11 = MCD-00635: Black Hat for switch TD0341X-G01-BLA; Part_Type: Misc; Manufacturer_Part_Number: 988.16.09.3.00003_SH-517; Manufacturer: JIUBABA; Part_Preference: Not recommended
L1 = MCD-00047: SMD Chip ferrite bead, 600R@100MHz +/-25%, 350mA, 500mohm DC, 0603, T=0.8mm; Manufacturer_Part_Number: FCM1608KF-601T03; Manufacturer: TAI-TECH; Part_Type: Inductor; Part_Preference: Recommended; Provided_By: SUBCO
R26 = MCD-00224: as R10 on sheet ST_LINK_V2-1
R29 = MCD-00219: as R6 on sheet ST_LINK_V2-1
R31-R34 = MCD-00052: Resistor,0R,0402,5%,1/16W; Manufacturer_Part_Number: RC0402JR-070RL; Manufacturer: YAGEO; Alternate_Manufacturer_Part_Number: RT0402FRE07100KL; Part_Preference: Recommended; ECCN_US: EAR99; ECCN_EU: NEC; Provided_By: SUBCO; Order_Code_RS: 618-5804
SB24 SB27 SB28 SB30 SB32 = MCD-00071: as SB11 on sheet ST_LINK_V2-1
SB29 SB31 SB33 = MCD-00072: as SB1 on sheet ST_LINK_V2-1
U7 = MCD-02301: MCU, ARM™-based 32-bit MCU Cortex-M0+, 32KB Flash, 6KB SRAM; Part_Type: IC; Part_Preference: Recommended; Manufacturer: STMICROELECTRONICS
X2 = MCD-01479: Crystal 32.768kHz, 6pF, -+20ppm, 80Kohm max, SMD; Part_Type: Crystal oscillator; Manufacturer_Part_Number: NX2012SA 32.768KHz EXS00A-MU00527; Manufacturer: NDK; BMS_Part_Number: 9157049; Part_Preference: Recommended; ECCN_US: EAR99; ECCN_EU: NEC; Provided_By: SUBCO
X3 = MCD-02262: Crystal, 48MHz, 7pF, +/-20 ppm, 80R, 1.6x1.2mm; Part_Type: Crystal oscillator; Manufacturer_Part_Number: NX1612SA-48MHZ-EXS00A-CS13734; Manufacturer: NDK; BMS_Part_Number: 9157042; Part_Preference: Recommended; ECCN_US: EAR99; ECCN_EU: NEC; Provided_By: SUBCO

## Sheet Power.SchDoc: Power
size A4; CompanyName: STMicroelectronics; Organization: Microcontrollers Division; SheetNumber: 5; SheetTotal: 7
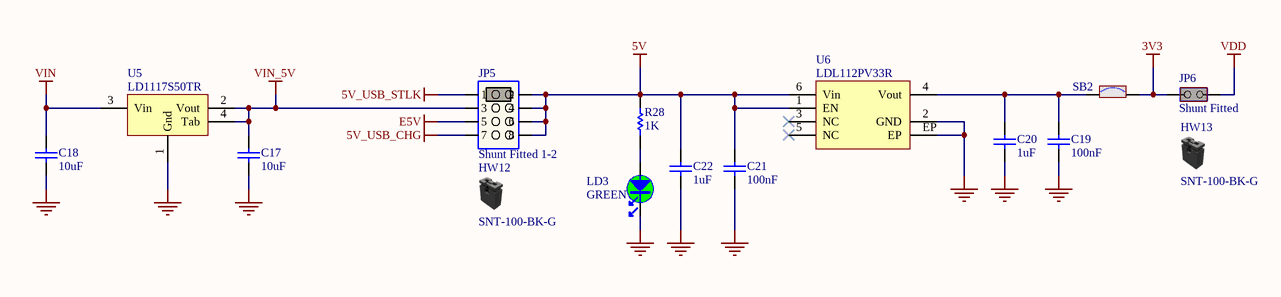
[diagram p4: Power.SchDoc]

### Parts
C17  value 10uF  [C0805]  (hidden comment: Capacitor)
C18  value 10uF  [C0805]  (hidden comment: Capacitor)
C19  value 100nF  [C0603]  (hidden comment: Capacitor)
C20  value 1uF  [C0603]  (hidden comment: Capacitor)
C21  value 100nF  [C0603]  (hidden comment: Capacitor)
C22  value 1uF  [C0603]  (hidden comment: Capacitor)
HW12  value SNT-100-BK-G  (hidden comment: Shunt Black 2.54mm)  (mechanical)
HW13  value SNT-100-BK-G  (hidden comment: Shunt Black 2.54mm)  (mechanical)
JP5  value Shunt Fitted 1-2  [CON_SAMTEC_TSW-104-07-X-D]  (hidden comment: Jumper_Header 4x2 Fitted 1-2)
JP6  value Shunt Fitted  [CON_SAMTEC_TSW-102-07-G-S]  (hidden comment: Jumper_Header 2x1 Fitted)
LD3  value GREEN  [LED_0603_GREEN]  (hidden comment: LED_green)
R28  value 1K  [R0603]  (hidden comment: Resistor)
SB2  SB_ON  [SOLDER-BRIDGE_R0603-0R]  (value not drawn)
U5  LD1117S50TR  [REG_SOT223-TAB]
U6  LDL112PV33R  [ICC_DFN6-EPAD_3X3_P095]

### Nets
3V3: JP6.2(NO) SB2.2
5V: C21.2 C22.2 JP5.2 JP5.4 JP5.6 JP5.8 R28.1 U6.1(EN) U6.6(Vin)
5V_USB_CHG: JP5.7
5V_USB_STLK: JP5.1
E5V: JP5.5
GND: C17.1 C18.1 C19.1 C20.1 C21.1 C22.1 LD3.2 U5.1(Gnd) U6.2(GND) U6.EP
VDD: JP6.1(COMMON)
VIN: C18.2 U5.3(Vin)
VIN_5V: C17.2 JP5.3 U5.2(Vout) U5.4(Tab)
NetC19_2: C19.2 C20.2 SB2.1 U6.4(Vout)
NetLD3_1: LD3.1 R28.2

Not connected (* = marked no-connect by the designer): U6 3(NC)* 5(NC)*

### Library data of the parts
C17 C18 = MCD-00014: Capacitor, MLCC, 10uF, 25V, X5R, +/-10%, 0805, T=0,85mm; Manufacturer_Part_Number: CC0805KRX5R8BB106; Manufacturer: YAGEO; Alternate_Manufacturer_Part_Number: GCM155R71C104KA55D; Alternate_Manufacturer: MURATA; Part_Preference: Recommended; ECCN_US: EAR99; ECCN_EU: NEC; Provided_By: SUBCO
C19 C21 = MCD-00211: as C1 on sheet ST_LINK_V2-1
C20 C22 = MCD-00010: as C6 on sheet ST_LINK_V2-1
HW12 HW13 = MCD-00043: as HW6 on sheet ST_LINK_V2-1
JP5 = MCD-00686: Header, 4x2, 2,54mm, VR, TH, Height 5.84mm/2.54mm - Shunt Fitted 1-2; Part_Type: Connector; Manufacturer_Part_Number: TSW-104-07-G-D; Manufacturer: SAMTEC; Part_Preference: Recommended
JP6 = MCD-00683: Header, 2x1, 2,54mm, VR, TH, Height 5.84mm/2.54mm - Shunt Fitted by default; Part_Type: Connector; Manufacturer_Part_Number: TSW-102-07-G-S; Manufacturer: SAMTEC; Alternate_Manufacturer_Part_Number: 313102S111116; Alternate_Manufacturer: LIANYI; Part_Preference: Recommended; Provided_By: SUBCO
LD3 = MCD-00050: LED, Green, 0603; Part_Type: Display; Manufacturer_Part_Number: 19-213SYGC/S530-E2/TR8; Manufacturer: EVERLIGHT; Alternate_Manufacturer_Part_Number: LG Q396-PS-35; Alternate_Manufacturer: OSRAM OPTO SEMICONDUCTORS; Part_Preference: Recommended; Provided_By: SUBCO; Order_Code_RS: 7730452
R28 = MCD-00070: as R16 on sheet ST_LINK_V2-1
SB2 = MCD-00071: as SB11 on sheet ST_LINK_V2-1
U5 = MCD-00088: IC REG LDO 5V 0.8A SOT223; Manufacturer: STMICROELECTRONICS; BMS_Part_Number: 9176133; Part_Preference: Recommended; Manufacturer_HQ_COO: EU; ECCN_US: EAR99; ECCN_EU: NEC; Provided_By: SUBCO with ST control
U6 = MCD-00664: 1.2 A low quiescent current LDO with reverse current protection; Part_Type: IC; Manufacturer: STMICROELECTRONICS; BMS_Part_Number: 9176253; Part_Preference: Recommended; Manufacturer_HQ_COO: EU

## Sheet HW_Mechanical_Parts.SchDoc: HW Mechanical parts
size A4; SheetNumber: 7; SheetTotal: 7
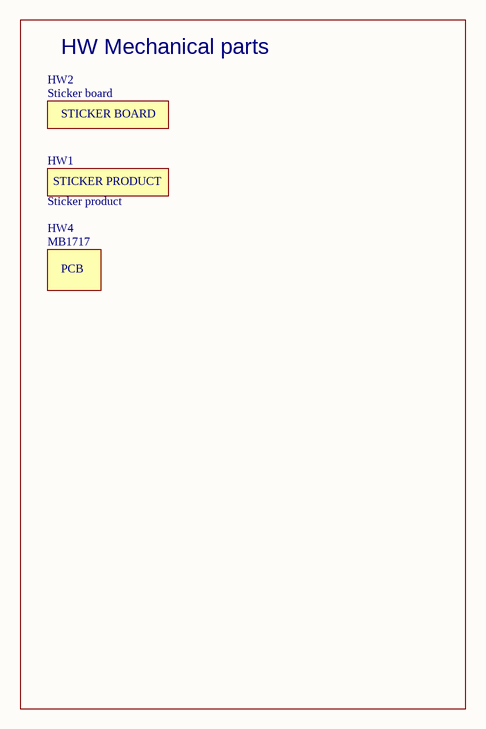
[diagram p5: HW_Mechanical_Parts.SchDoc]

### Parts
HW1  value Sticker product  [STICKER_PRODUCT_25X9]  (hidden comment: STICKER_PRODUCT)  (no BOM)
HW2  value Sticker board  [STICKER_BOARD_25X9]  (hidden comment: STICKER_BOARD)  (no BOM)
HW4  value MB1717  (hidden comment: PCB)  (mechanical)

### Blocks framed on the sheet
HW Mechanical parts: HW1 HW2 HW4

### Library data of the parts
HW1 = MCD-00547: Sticker product 25x9 mm; Part_Type: Misc; Part_Preference: Recommended
HW2 = MCD-00235: Sticker Board 25x9 mm; Part_Type: Misc; Part_Preference: Recommended
HW4 = MCD-02488: MB1717 PCB; Part_Preference: Recommended; Provided_By: SUBCO

## Sheet Arduino_Morpho_connectors.SchDoc: Connectors
size A4; CompanyName: STMicroelectronics; Organization: Microcontrollers Division; SheetNumber: 4; SheetTotal: 7
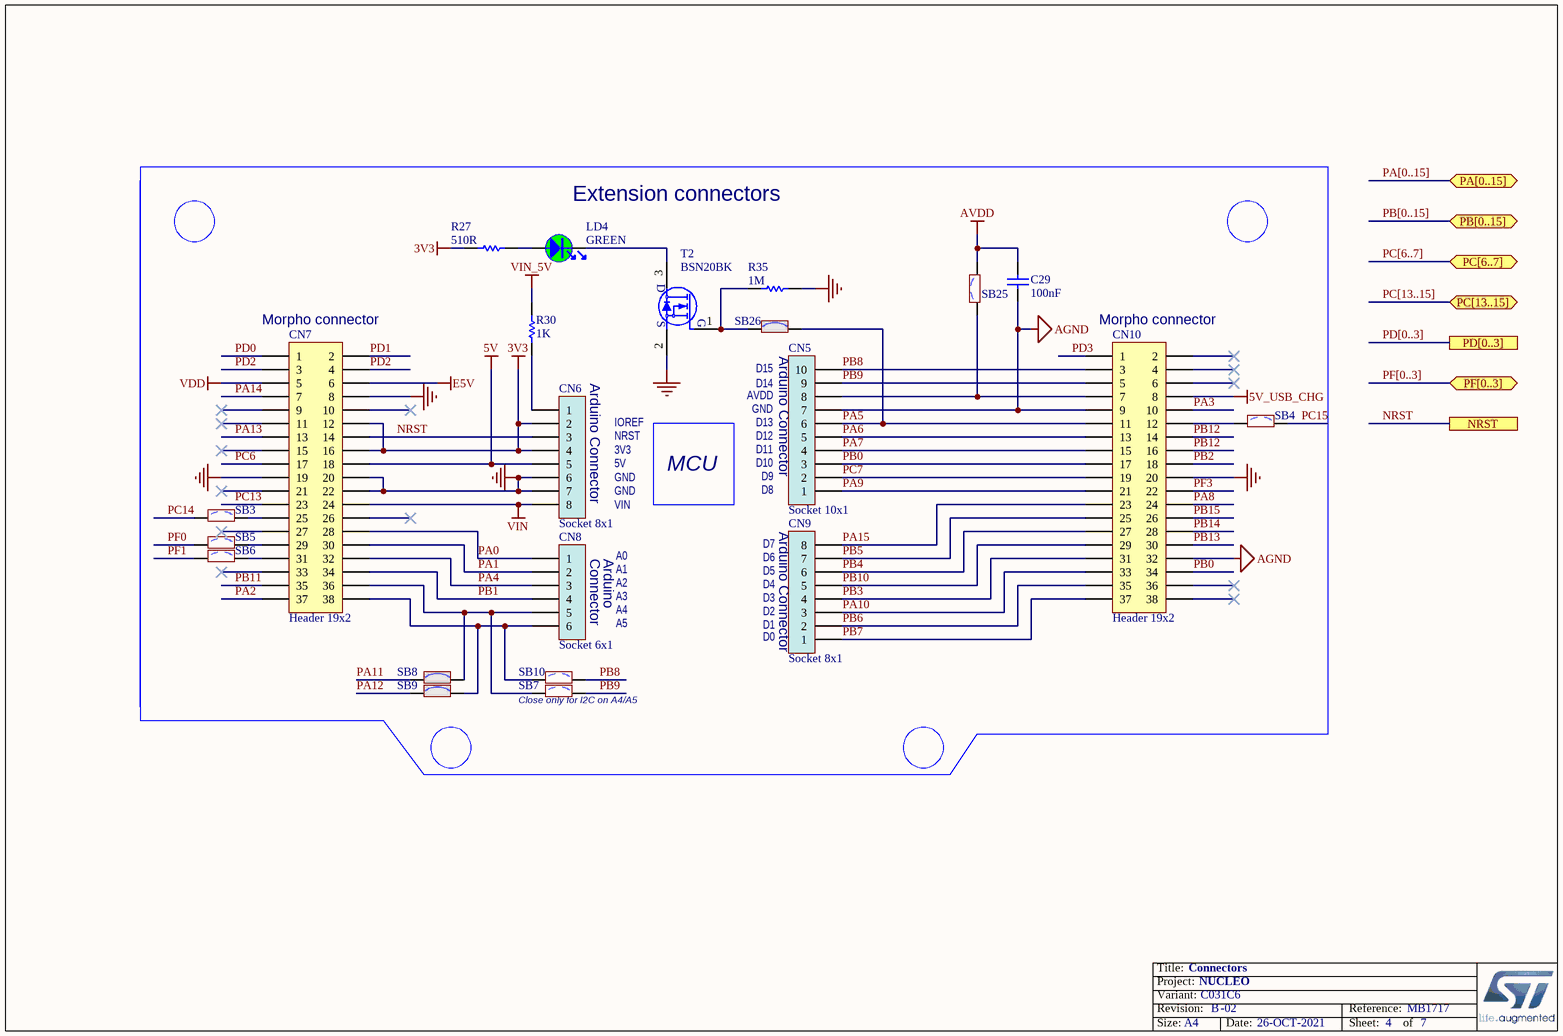
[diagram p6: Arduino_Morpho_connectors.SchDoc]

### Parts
C29  value 100nF  [C0603]  (hidden comment: Capacitor)
CN5  Socket 10x1  [CON_SAMTEC_SSW-110-03-X-S]
CN6  Socket 8x1  [CON_SAMTEC_SSW-108-03-X-S]
CN7  Header 19x2  [CON_SAMTEC_TSW-119-09-X-D]
CN8  Socket 6x1  [CON_SAMTEC_SSW-106-03-X-S]
CN9  Socket 8x1  [CON_SAMTEC_SSW-108-03-X-S]
CN10  Header 19x2  [CON_SAMTEC_TSW-119-09-X-D]
LD4  value GREEN  [LED_0603_GREEN]  (hidden comment: LED_green)
R27  value 510R  [R0603]  (hidden comment: Resistor)
R30  value 1K  [R0603]  (hidden comment: Resistor)
R35  value 1M  [R0603]  (hidden comment: Resistor)
SB3  SB_OFF  [SOLDER-BRIDGE_R0603-0R]  (value not drawn)
SB4  SB_OFF  [SOLDER-BRIDGE_R0603-0R]  (value not drawn)
SB5  SB_OFF  [SOLDER-BRIDGE_R0603-0R]  (value not drawn)
SB6  SB_OFF  [SOLDER-BRIDGE_R0603-0R]  (value not drawn)
SB7  SB_OFF  [SOLDER-BRIDGE_R0603-0R]  (value not drawn)
SB8  SB_ON  [SOLDER-BRIDGE_R0603-0R]  (value not drawn)
SB9  SB_ON  [SOLDER-BRIDGE_R0603-0R]  (value not drawn)
SB10  SB_OFF  [SOLDER-BRIDGE_R0603-0R]  (value not drawn)
SB25  SB_OFF  [SOLDER-BRIDGE_R0603-0R]  (value not drawn)
SB26  SB_ON  [SOLDER-BRIDGE_R0603-0R]  (value not drawn)
T2  value BSN20BK  [MOS_SOT23]  (hidden comment: BSN20)

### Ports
NRST, PA[0..15] (bidir), PB[0..15] (bidir), PC[6..7] (bidir), PC[13..15] (bidir), PD[0..3], PF[0..3] (bidir)

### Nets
3V3: CN6.2 CN6.4 CN7.12 CN7.16 R27.2
5V: CN6.5 CN7.18
5V_USB_CHG: CN10.8
AGND: C29.1 CN5.7 CN10.9 CN10.32
AVDD: C29.2 SB25.2
E5V: CN7.6
GND: CN6.6 CN6.7 CN7.8 CN7.19 CN7.20 CN7.22 CN10.20 R35.2 T2.2(S)
VDD: CN7.5
VIN: CN6.8 CN7.24
VIN_5V: R30.1
NRST: CN6.3 CN7.14 ; port NRST
PA0: CN7.28 CN8.1
PA1: CN7.30 CN8.2
PA2: CN7.37
PA3: CN10.10
PA4: CN7.32 CN8.3
PA5: CN5.6 CN10.11 SB26.2
PA6: CN5.5 CN10.13
PA7: CN5.4 CN10.15
PA8: CN10.24
PA9: CN5.1 CN10.21
PA10: CN9.3 CN10.33
PA11: SB8.1
PA12: SB9.1
PA13: CN7.13
PA14: CN7.7
PA15: CN9.8 CN10.23
PB0: CN5.3 CN10.17 CN10.34
PB1: CN7.34 CN8.4
PB2: CN10.18
PB3: CN9.4 CN10.31
PB4: CN9.6 CN10.27
PB5: CN9.7 CN10.25
PB6: CN9.2 CN10.35
PB7: CN9.1 CN10.37
PB8: CN5.10 CN10.3 SB10.2
PB9: CN5.9 CN10.5 SB7.2
PB10: CN9.5 CN10.29
PB11: CN7.35
PB12: CN10.14 CN10.16
PB13: CN10.30
PB14: CN10.28
PB15: CN10.26
PC6: CN7.17
PC7: CN5.2 CN10.19
PC13: CN7.23
PC14: SB3.1
PC15: SB4.2
PD0: CN7.1
PD1: CN7.2
PD2: CN7.3 CN7.4
PD3: CN10.1
PF0: SB5.1
PF1: SB6.1
PF3: CN10.22
NetCN5_8: CN5.8 CN10.7 SB25.1
NetCN6_1: CN6.1 R30.2
NetCN7_25: CN7.25 SB3.2
NetCN7_29: CN7.29 SB5.2
NetCN7_31: CN7.31 SB6.2
NetCN7_36: CN7.36 CN8.5 SB7.1 SB8.2
NetCN7_38: CN7.38 CN8.6 SB9.2 SB10.1
NetCN10_12: CN10.12 SB4.1
NetLD4_1: LD4.1 R27.1
NetLD4_2: LD4.2 T2.3(D)
NetR35_1: R35.1 SB26.1 T2.1(G)

Not connected (* = marked no-connect by the designer): CN7 9* 10* 11* 15* 21* 26* 27* 33*; CN10 2* 4* 6* 36* 38*

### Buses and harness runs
bus PA[0..15] = port PA[0..15]
bus PB[0..15] = port PB[0..15]
bus PC[6..7] = port PC[6..7]
bus PC[13..15] = port PC[13..15]
bus PD[0..3] = port PD[0..3]
bus PF[0..3] = port PF[0..3]

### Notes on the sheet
- (near LD4) Extension connectors
- (near CN7) Morpho connector
- (near CN6) Arduino Connector
- D15
- Arduino Connector
- (near CN10) Morpho connector
- NRST
- IOREF
- AVDD
- (near CN5) GND
- (near CN5) D12
- (near CN5) D13
- D14
- GND
- VIN
- 5V
- 3V3
- MCU
- (near CN5) D10
- (near CN5) D11
- (near CN5) D9
- D8
- (near CN8) Connector
- (near CN8) Arduino
- A0
- A1
- A2
- (near CN9) D5
- (near CN9) D6
- D7
- (near CN9) Arduino Connector
- A5
- A3
- A4
- (near CN9) D0
- (near CN9) D1
- (near CN9) D2
- (near CN9) D3
- (near CN9) D4
- (near SB7) Close only for I2C on A4/A5

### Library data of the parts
C29 = MCD-00211: as C1 on sheet ST_LINK_V2-1
CN5 = MCD-00262: Socket, 10x1, 2.54mm, VR, TH, Height 8.51mm/10mm; Manufacturer_Part_Number: SSW-110-03-G-S; Manufacturer: SAMTEC; Part_Type: Connector; Part_Preference: Recommended; Provided_By: SUBCO
CN6 = MCD-00261: Socket, 8x1, 2.54mm, VR, TH, Height 8.51mm/10mm; Manufacturer_Part_Number: SSW-108-03-G-S; Manufacturer: SAMTEC; Part_Type: Connector; Part_Preference: Recommended; Provided_By: SUBCO
CN7 CN10 = MCD-00213: Header, 19x2, 2,54mm, VR, TH, Height 5.84mm/10.16mm; Manufacturer_Part_Number: TSW-119-09-G-D; Manufacturer: SAMTEC; Part_Type: Connector; Part_Preference: Recommended; Provided_By: SUBCO
CN8 = MCD-00260: Socket, 6x1, 2.54mm, VR, TH, Height 8.51mm/10mm; Part_Type: Connector; Manufacturer_Part_Number: SSW-106-03-G-S; Manufacturer: SAMTEC; Part_Preference: Recommended; Provided_By: SUBCO
CN9 = MCD-00261: Socket, 8x1, 2.54mm, VR, TH, Height 8.51mm/10mm; Part_Type: Connector; Manufacturer_Part_Number: SSW-108-03-G-S; Manufacturer: SAMTEC; Part_Preference: Recommended; Provided_By: SUBCO
LD4 = MCD-00050: as LD3 on sheet Power
R27 = MCD-00225: Resistor,510R,0603,1%,1/10W; Manufacturer_Part_Number: RC0603FR-07510RL; Manufacturer: YAGEO; Alternate_Manufacturer_Part_Number: RT0402FRE07100KL; Part_Preference: Recommended; ECCN_US: EAR99; ECCN_EU: NEC; Provided_By: SUBCO
R30 = MCD-00070: as R16 on sheet ST_LINK_V2-1
R35 = MCD-00257: Resistor,1M,0603,1%,1/10W; Manufacturer_Part_Number: RC0603FR-071ML; Manufacturer: YAGEO; Alternate_Manufacturer_Part_Number: RT0402FRE07100KL; Part_Preference: Recommended; ECCN_US: EAR99; ECCN_EU: NEC; Provided_By: SUBCO
SB3 SB4 SB7 SB10 SB25 = MCD-00072: as SB1 on sheet ST_LINK_V2-1
SB5 SB6 = MCD-00072: Solder Bridge OFF; Part_Type: Misc; Manufacturer_Part_Number: RC0603JR-070RL; Manufacturer: YAGEO; Part_Preference: Recommended; Component_Country_Of_Origin: China
SB8 SB9 SB26 = MCD-00071: as SB11 on sheet ST_LINK_V2-1
T2 = MCD-01969: Transistor, N-channel enhancement mode field-effect transistor; Manufacturer: NEXPERIA; Part_Preference: Recommended; Order_Code_RS: 136-4845

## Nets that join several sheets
3V3: ST_LINK_V2-1 (R23.1), Power (JP6.2 SB2.2), Arduino_Morpho_connectors (5 pins)
5V: ST_LINK_V2-1 (D1.1), Power (9 pins), Arduino_Morpho_connectors (CN6.5 CN7.18)
5V_USB_CHG: ST_LINK_V2-1 (10 pins), Power (JP5.7), Arduino_Morpho_connectors (CN10.8)
5V_USB_STLK: ST_LINK_V2-1 (C14.2 U3.1), Power (JP5.1)
AGND: STM32_microcontroller_IOs (C31.1 SB28.2), Arduino_Morpho_connectors (C29.1 CN5.7 CN10.9 CN10.32)
AVDD: STM32_microcontroller_IOs (C31.2 SB30.1 U7.5), Arduino_Morpho_connectors (C29.2 SB25.2)
E5V: ST_LINK_V2-1 (D4.1), Power (JP5.5), Arduino_Morpho_connectors (CN7.6)
GND: ST_LINK_V2-1 (47 pins), STM32_microcontroller_IOs (16 pins), Power (10 pins), Arduino_Morpho_connectors (9 pins)
VDD: STM32_microcontroller_IOs (5 pins), Power (JP6.1), Arduino_Morpho_connectors (CN7.5)
VIN: Power (C18.2 U5.3), Arduino_Morpho_connectors (CN6.8 CN7.24)
VIN_5V: ST_LINK_V2-1 (D5.1), Power (C17.2 JP5.3 U5.2 U5.4), Arduino_Morpho_connectors (R30.1)
MCO: ST_LINK_V2-1 (SB20.2), STM32_microcontroller_IOs (SB29.2)
NRST: ST_LINK_V2-1 (SB23.2), STM32_microcontroller_IOs (B2.3 B2.4 C28.2 U7.10), Arduino_Morpho_connectors (CN6.3 CN7.14)
PA0: STM32_microcontroller_IOs (U7.11), Arduino_Morpho_connectors (CN7.28 CN8.1)
PA1: STM32_microcontroller_IOs (U7.12), Arduino_Morpho_connectors (CN7.30 CN8.2)
PA2: STM32_microcontroller_IOs (SB27.2 U7.13), Arduino_Morpho_connectors (CN7.37)
PA3: STM32_microcontroller_IOs (SB32.2 U7.14), Arduino_Morpho_connectors (CN10.10)
PA4: STM32_microcontroller_IOs (U7.15), Arduino_Morpho_connectors (CN7.32 CN8.3)
PA5: STM32_microcontroller_IOs (U7.16), Arduino_Morpho_connectors (CN5.6 CN10.11 SB26.2)
PA6: STM32_microcontroller_IOs (U7.17), Arduino_Morpho_connectors (CN5.5 CN10.13)
PA7: STM32_microcontroller_IOs (U7.18), Arduino_Morpho_connectors (CN5.4 CN10.15)
PA8: STM32_microcontroller_IOs (U7.28), Arduino_Morpho_connectors (CN10.24)
PA9: STM32_microcontroller_IOs (U7.29), Arduino_Morpho_connectors (CN5.1 CN10.21)
PA10: STM32_microcontroller_IOs (U7.32), Arduino_Morpho_connectors (CN9.3 CN10.33)
PA11: STM32_microcontroller_IOs (U7.33), Arduino_Morpho_connectors (SB8.1)
PA12: STM32_microcontroller_IOs (U7.34), Arduino_Morpho_connectors (SB9.1)
PA13: ST_LINK_V2-1 (SB17.1), STM32_microcontroller_IOs (U7.35), Arduino_Morpho_connectors (CN7.13)
PA14: ST_LINK_V2-1 (SB13.1), STM32_microcontroller_IOs (U7.36), Arduino_Morpho_connectors (CN7.7)
PA15: STM32_microcontroller_IOs (U7.37), Arduino_Morpho_connectors (CN9.8 CN10.23)
PB0: STM32_microcontroller_IOs (U7.19), Arduino_Morpho_connectors (CN5.3 CN10.17 CN10.34)
PB1: STM32_microcontroller_IOs (U7.20), Arduino_Morpho_connectors (CN7.34 CN8.4)
PB2: STM32_microcontroller_IOs (U7.21), Arduino_Morpho_connectors (CN10.18)
PB3: STM32_microcontroller_IOs (U7.42), Arduino_Morpho_connectors (CN9.4 CN10.31)
PB4: STM32_microcontroller_IOs (U7.43), Arduino_Morpho_connectors (CN9.6 CN10.27)
PB5: STM32_microcontroller_IOs (U7.44), Arduino_Morpho_connectors (CN9.7 CN10.25)
PB6: STM32_microcontroller_IOs (SB31.2 U7.45), Arduino_Morpho_connectors (CN9.2 CN10.35)
PB7: STM32_microcontroller_IOs (SB33.2 U7.46), Arduino_Morpho_connectors (CN9.1 CN10.37)
PB8: STM32_microcontroller_IOs (U7.47), Arduino_Morpho_connectors (CN5.10 CN10.3 SB10.2)
PB9: STM32_microcontroller_IOs (U7.48), Arduino_Morpho_connectors (CN5.9 CN10.5 SB7.2)
PB10: STM32_microcontroller_IOs (U7.22), Arduino_Morpho_connectors (CN9.5 CN10.29)
PB11: STM32_microcontroller_IOs (U7.23), Arduino_Morpho_connectors (CN7.35)
PB12: STM32_microcontroller_IOs (U7.24), Arduino_Morpho_connectors (CN10.14 CN10.16)
PB13: STM32_microcontroller_IOs (U7.25), Arduino_Morpho_connectors (CN10.30)
PB14: STM32_microcontroller_IOs (U7.26), Arduino_Morpho_connectors (CN10.28)
PB15: STM32_microcontroller_IOs (U7.27), Arduino_Morpho_connectors (CN10.26)
PC6: STM32_microcontroller_IOs (U7.30), Arduino_Morpho_connectors (CN7.17)
PC7: STM32_microcontroller_IOs (U7.31), Arduino_Morpho_connectors (CN5.2 CN10.19)
PC13: STM32_microcontroller_IOs (SB24.1 U7.1), Arduino_Morpho_connectors (CN7.23)
PC14: STM32_microcontroller_IOs (R31.2 U7.2), Arduino_Morpho_connectors (SB3.1)
PC15: STM32_microcontroller_IOs (R32.2 U7.3), Arduino_Morpho_connectors (SB4.2)
PD0: STM32_microcontroller_IOs (U7.38), Arduino_Morpho_connectors (CN7.1)
PD1: STM32_microcontroller_IOs (U7.39), Arduino_Morpho_connectors (CN7.2)
PD2: STM32_microcontroller_IOs (U7.40), Arduino_Morpho_connectors (CN7.3 CN7.4)
PD3: STM32_microcontroller_IOs (U7.41), Arduino_Morpho_connectors (CN10.1)
PF0: STM32_microcontroller_IOs (R33.2 SB29.1 U7.8), Arduino_Morpho_connectors (SB5.1)
PF1: STM32_microcontroller_IOs (R34.2 U7.9), Arduino_Morpho_connectors (SB6.1)
PF3: STM32_microcontroller_IOs (U7.4), Arduino_Morpho_connectors (CN10.22)

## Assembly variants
C031C6: not fitted C11 C25 C26 C29 JP6 R2 R3 R33 R34 SB1 SB3 SB4 SB5 SB6 SB7 SB10 SB12 SB14 SB16 SB18 SB20 SB25 SB29 SB31 SB33 X3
